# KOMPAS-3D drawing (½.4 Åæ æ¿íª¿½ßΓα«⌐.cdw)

Views: Вид 1
Referenced files in C:\Program Files\ASCON\KOMPAS-3D V10\Sys\: SPDS.lcs, Graphic.lcs
Referenced files in \\F-server\проектирование\Проекты\РЗА и ПА Тюменские РС\4. Проект\ЭП\Туринская\Рабочая документация\: план располодения оборудования на ПС.cdw
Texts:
  Текст на чертеже
  Размерные надписи
  Шероховатость
  Линия-выноска #1
  Линия-выноска #2
  Линия-выноска #3
  Отклонения формы и база
  Заголовок таблицы
  Ячейка таблицы
  Стрелка вида
  Обозначение изменения
  Фигурная скобка
  Номер узла
  Марка координационной оси
  VRCB
  Выносная надпись
  Обозначение узла
  Марка/позиционное обозначение с линией-выноской
  Марка/позиционное обозначение на линии
  Марка/позиционное обозначение без линии-выноски
  Лит-Масса-Масштаб
  Материал-Предприятие
  Title Specification
  Body Specification ( left align )
  Body Specificaton ( centered )
  Без имени
  Normal
  heading 1
  Знак Знак Знак Знак Знак Знак
  Verdana
  Body Text
  MS Sans Serif
  Txt
  Simplex
  TXT
  Обычный
  Термин
  Список определений
  Адрес
  Цитаты
  Форматированный
  Courier New
  Z-конец формы
  Z-начало формы
  Additional DXF text style 0
  Абзац Знак
  Body Text 3
  Title
  ТекстШаг1
  Шрифт 2.5
  Заголовки
  txt
  heading 2
  AGOpus
  footer
  Денис
  RUSTXT
  Обычный (веб)
  ООббыыччнныыйй
  Definition Term
  Definition List
  Address
  Blockquote
  Preformatted
  z-Bottom of Form
  z-Top of Form
  header
  NormalParagraphStyle
  ссылки
  Подпись в квадратике
  табл
  цепи
  Маркировка
  клеммы, контакты
  тексты табл
  Тексты. 3,2
  ЗОНА_привяз
  текст переноса
  ТТееррммиинн
  ССппииссоокк ооппррееддееллеенниийй
  ААддрреесс
  ЦЦииттааттыы
  ФФооррммааттиирроовваанннныыйй
  Z-ккооннеецц ффооррммыы
  Z-ннааччааллоо ффооррммыы
  GOST 2.304 type A
  rustxt
  heading 8
  heading 3
  heading 6
  heading 7
  russ
  heading 4
  heading 5
  heading 9
  HeliosLight
  Pa3
  Pa1
  Три с половиной
  style2
  Table Contents
  Table Heading
  ГОСТ_МНЕ
  ESK - Обозначение
  маркировка
  ISOCP
  ROMANS
  SIMPLEX
  Текст 3,5
  Tahoma
  CNBNDG+TimesNewRoman
  Subtitle
  FR5
  подписи
  Аппараты
  Ссылки
  Состав чартежа
  ячейка табл.
  Пояснения
  Клеммник текст
  .07 RGB_0_0_0 i0b0u0
  CM12
  romans
  текст табл
  Body Text Indent 3
  Основной текст с отступом 3
  gif
  Пояснения 2
  romanc
  eskd1
  Pa15
  Pa18
  ISOCPEUR
  CC С?т?и?л?ь? П?о? ц?е?н?т?р?у?
  Normal (Web)
  ошиноска 110
  лотки
  поз
  Демонтаж
  Монтаж
  Поз.
  Перечень элементов
  Кол.
  ед., кг
  Приме-
  чание
  Трансформатор силовой маслянный
  с 2 комплектами заземляющих ножей
  Разъединитель трёхполюсный 110кВ
  Трансформатор трехфазный
  двухобмоточный масляный
  ТМ-400/10-0,4
  Выключатель маслянный колонковый
  ВМТ-110Б-25/1250 УХЛ1
  Выключатель элегазовый 110 кВ
  ТРНДЦН-25000/110 У1
  трехобмоточный
  РДЗ 2-110/1000 У1
  с 1 комплектом заземляющих ножей
  РДЗ 1-110/1000 У1
  сущ.
  EXLIM R 120
  Ограничитель перенапряжения 110 кВ
  SGF 123
  Трансформатор тока 110 кВ
  ТФЗМ-110Б-IV У1
  Трансформатор напряжения 110 кВ
  НКФ-110-83 У1
  ВЧ-заградитель 110 кВ
  ВЗ-630
  Конденсатор связи 110 кВ
  СМПВ-110/ 3 -6,4
  Изолятор опорный 110 кВ
  Фильтр присоединения 110кВ
  ФП 6400
  Разъединитель РВО-10
  РВО-10/400
  Разъединитель однополюсный 10 кВ
  проект.
  ТСН 1
  ТСН 2
  Экспликация зданий и сооружений
  Номер
  на плане
  Постоянные здания и сооружения
  ОПУ
  ЗРУ 10 кВ
  Трансформатор 1Т, маслоприемник
  Трансформатор 2Т, маслоприемник
  Существующее
  Существующий
  Временные здания и сооружения
  III
  Вагон-дом для кратковременного отдых рабочих
  Уборная
  Дизельная электростанция
  Контейнеры для ТБО (0,75м 3 ) и жидких хоз.-быт.стоков(1м 3 )
  «Екатерина» 9,0х3,0
  Туалетная кабина "Люкс"
  ОАО ПКТИпромстрой
  АДС 45-Т400 РЯ
  - предупреждающий знак
  "Опасно. Возможно падение груза"
  "Опасность поражения электрическим током"
  - стоянка крана во время производства работ
  - стенд с противопожарным инвентарем
  - знак ограничения поворота стрелы
  - опасная зона работы при перемещении грузов
  Условные обозначения:
  Примечания:
  1. Для нужд строительства (размещение задействованного в строительстве персонала, обеспечение электроэнергией) использовать временные мобильные
  инвентарные здания;
  2. При выполнении всех строительно-монтажных работ на площадке необходимо руководствоваться требованиями СНиП 12-03-2001 "Безопасность труда в
  строительстве. Общие требования",  СНиП 12-04-2002 "Безопасность труда в строительстве. Строительное производство", а также  ПОТ-РМ-016-2001/
  РД 153-34.0-03.150-00 "Межотраслевые правила по охране труда (правила безопасности) при эксплуатации электроустановок";
  3. Наружное освещение строительной площадки осуществляется за счет существующего освещения;
  4. Под временные сооружения (поз. II, III и IV) устраивается площадка из дорожных плит ПД 60-20 на  щебеночном основании толщиной 15см;
  5. На период строительства для электроснабжения временных зданий и сооружений использовать дизельную электростанцию. Прокладку  кабеля от
  дизельной электростанции до вагончиков выполнить в воздушном исполнении в гофрированной трубе диаметром 30 мм, на вагончиках кабель закрепить
  скобами. Щиток временного электроснабжения навесить на стенку вагона-дома для отдыха рабочих;
  6. При выполнении монтажных работ использовать инвентарные лестницы и леса;
  7. На паспорте-стенде строительного объекта  должен быть план пожарной защиты с нанесенными строящимися и вспомогательными зданиями и
  сооружениями, въездами, подъездами, местонахождениями водоисточников, средств пожаротушения и связи (согласно ППБ-01-03 п.575);
  8. Тонкой линией изображено существующее оборудование, замена которого проектом не предусматривается,  утолщенной - демонтируемое оборудование.
  - паспорт-стенд строительного
  объекта
  - запрещающий знак ограничения
  скорости движения автомобиля
  КМУ ИНМАН ИМ-150
  K5LT_BASIC_RGB_0_0_255_THICK_0.6
  Стили документа
  Бортовой автомобиль КамАЗ 43114-027-02
  АТ ППР#010#0104
  ГИП
  Н.контр.
  Гл.спец.
  Провер.
  Разраб.
  Перезавод ВЛ на ПС Тюмень. Реконструкция устройств
  РЗ и ПА на обратных концах отходящих ВЛ,
  ВОЛС Тюменского ТПО
  ПС 110/10 кВ Сибжилстрой
  Матвеев
  Ромин
  Шашерин
  Королева
  Микрюков
  Строительный генеральный план
  Ведомость эскизного проекта
Dimensions and other numbers on the sheet: 16/01-ПОД; 7; 2,5; 1,8; 2.5; 3,2_; 3.5; 3,2; 2,5 (контакты, клеммы); 3,2 (надписи); 3,2 (Зоны); 5; 2,5_01; 2,5_3; 3,5_01; 3,5_tabl; 5_заголовок; 2,3_; 3,2_зона не привяз; 3,5; 3.2 маркировка; 3,2 элементы; 3,2 линия; 3,2 таблица; 2,5 грязносинь; 2.5 курсив; 2.5_Э5_надписи; 2.5_Э5_ссылки; 2.5_кабель; 3.2; 2.5 надписи; 3 и 5; 5,0_белый_подчёркнутый; 3.2 фиол; 3.2 (текст); 0 i0b0u0; 1; 2; 3; 4; 6; 145 РМ 40-20; 14; 11; 21; 4000; 5000; 3000; 4500; 4900; 8100; 11000; 5100; 10000; 7500; 6000; 14000; 7000; 1000; 3700; 8; 9; 10; 12; 13; 33; 16; 17; 18; 19; 20; 15; 50; 105000; 157000; 22000; 7,5; 5,5; 13,2; 11,2; 05.13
